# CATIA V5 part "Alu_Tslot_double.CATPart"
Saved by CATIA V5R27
Part number: Tslotted_double
Revision: ANY
Definition: UNKNOWN
Nomenclature: Tslotted_44in
Source: Unknown
Bounding box of the stored display mesh (mm): x -19.05 to 19.05, y -19.05 to 19.05, z -381 to 381
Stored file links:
  \\triton.meca.polymtl.ca\usagers\zaoue\profiles\Desktop\varm_ass\structure prismatique\Alu_Tslot_double.CATPart
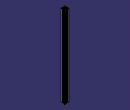
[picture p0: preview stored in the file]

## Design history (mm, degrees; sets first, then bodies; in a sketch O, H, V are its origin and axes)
Body1 "Boss-Extrude1" (main body)
  Solid1: solid without history
  Sketch1 on face of Solid1, origin (0, 19.05, 1524), H (1, 0, 0), V (0, 0, -1)
    point P1 (0, 1524)
    line L1 (-90.0378, 1905) -> (-90.0378, 1143)
    line L2 (-90.0378, 1143) -> (90.0378, 1143)
    line L3 (90.0378, 1143) -> (90.0378, 1905)
    line L4 (90.0378, 1905) -> (-90.0378, 1905)
    reference intersected line E1 through (0, 1524) direction (1, 0) from xy-plane
    reference intersected line E2 through (0, 0) direction (0, 1) from yz-plane
    distance L4 L2 = 762
    vertical: L1 V, L3 V
    horizontal: L2 H, L4 H
    equidistance: L1 L3 P1, L2 L4 P1
    coincidence: E1 P1, P1 E2
  Pocket1: profile Sketch1, direction (0, -1, 0), through (limit type 6), outer side
  Sketch2 on face of Pocket1 from Sketch1.L4, origin (0, 0, -381), H (1, 0, 0), V (0, -1, 0)
    projected arc E1 centre (-15.0939, 19.0563) radius 0.7684 from (-15.8623, 19.05) to (-14.3256, 19.05) ccw from edge [face of Pocket1 from Sketch1.L4 | face of Solid1]
    point P1 (-15.8623, 19.05)
    point P2 (-14.3256, 19.05)
    projected arc E2 centre (-8.7376, 19.05) radius 0.762 from (-9.4996, 19.05) to (-7.9756, 19.05) ccw from edge [face of Pocket1 from Sketch1.L4 | face of Solid1]
    point P3 (-9.4996, 19.05)
    point P4 (-7.9756, 19.05)
    projected arc E3 centre (-19.0564, 15.0939) radius 0.7684 from (-19.05, 14.3256) to (-19.05, 15.8623) ccw from edge [face of Pocket1 from Sketch1.L4 | face of Solid1]
    point P5 (-19.05, 14.3256)
    point P6 (-19.05, 15.8623)
    projected arc E4 centre (-19.05, 8.7376) radius 0.762 from (-19.05, 7.9756) to (-19.05, 9.4996) ccw from edge [face of Pocket1 from Sketch1.L4 | face of Solid1]
    point P7 (-19.05, 7.9756)
    point P8 (-19.05, 9.4996)
    line L1 (-15.8623, 19.05) -> (-14.3256, 19.05)
    reference projected line E5 (-9.4996, 19.05) -> (-14.3256, 19.05) from edge [face of Solid1 | face of Pocket1 from Sketch1.L4]
    line L2 (-9.4996, 19.05) -> (-7.9756, 19.05)
    line L3 (-19.05, 15.8623) -> (-19.05, 14.3256)
    reference projected line E6 (-19.05, 14.3256) -> (-19.05, 9.4996) from edge [face of Solid1 | face of Pocket1 from Sketch1.L4]
    line L4 (-19.05, 9.4996) -> (-19.05, 7.9756)
    reference intersected line E7 through (0, 0) direction (0, 1) from yz-plane
    point P11 (15.8623, 19.05)
    point P12 (14.3256, 19.05)
    point P13 (9.4996, 19.05)
    point P14 (7.9756, 19.05)
    point P15 (19.05, 14.3256)
    point P16 (19.05, 15.8623)
    point P17 (19.05, 7.9756)
    point P18 (19.05, 9.4996)
    line L5 (15.8623, 19.05) -> (14.3256, 19.05)
    line L6 (9.4996, 19.05) -> (7.9756, 19.05)
    line L7 (19.05, 15.8623) -> (19.05, 14.3256)
    line L8 (19.05, 9.4996) -> (19.05, 7.9756)
    arc A1 centre (15.0939, 19.0563) radius 0.7684 from (15.8623, 19.05) to (14.3256, 19.05) cw
    arc A2 centre (8.7376, 19.05) radius 0.762 from (9.4996, 19.05) to (7.9756, 19.05) cw
    arc A3 centre (19.0564, 15.0939) radius 0.7684 from (19.05, 14.3256) to (19.05, 15.8623) cw
    arc A4 centre (19.05, 8.7376) radius 0.762 from (19.05, 7.9756) to (19.05, 9.4996) cw
    reference intersected line E8 through (0, 0) direction (1, 0) from zx-plane
    point P21 (-15.8623, -19.05)
    point P22 (-14.3256, -19.05)
    point P23 (-9.4996, -19.05)
    point P24 (-7.9756, -19.05)
    point P25 (-19.05, -14.3256)
    point P26 (-19.05, -15.8623)
    point P27 (-19.05, -7.9756)
    point P28 (-19.05, -9.4996)
    point P29 (15.8623, -19.05)
    point P30 (14.3256, -19.05)
    point P31 (9.4996, -19.05)
    point P32 (7.9756, -19.05)
    point P33 (19.05, -14.3256)
    point P34 (19.05, -15.8623)
    point P35 (19.05, -7.9756)
    point P36 (19.05, -9.4996)
    line L9 (-15.8623, -19.05) -> (-14.3256, -19.05)
    line L10 (-9.4996, -19.05) -> (-7.9756, -19.05)
    line L11 (-19.05, -15.8623) -> (-19.05, -14.3256)
    line L12 (-19.05, -9.4996) -> (-19.05, -7.9756)
    line L13 (15.8623, -19.05) -> (14.3256, -19.05)
    line L14 (9.4996, -19.05) -> (7.9756, -19.05)
    line L15 (19.05, -15.8623) -> (19.05, -14.3256)
    line L16 (19.05, -9.4996) -> (19.05, -7.9756)
    arc A5 centre (15.0939, -19.0563) radius 0.7684 from (15.8623, -19.05) to (14.3256, -19.05) ccw
    arc A6 centre (8.7376, -19.05) radius 0.762 from (9.4996, -19.05) to (7.9756, -19.05) ccw
    arc A7 centre (19.0564, -15.0939) radius 0.7684 from (19.05, -14.3256) to (19.05, -15.8623) ccw
    arc A8 centre (19.05, -8.7376) radius 0.762 from (19.05, -7.9756) to (19.05, -9.4996) ccw
    arc A9 centre (-15.0939, -19.0563) radius 0.7684 from (-15.8623, -19.05) to (-14.3256, -19.05) cw
    arc A10 centre (-8.7376, -19.05) radius 0.762 from (-9.4996, -19.05) to (-7.9756, -19.05) cw
    arc A11 centre (-19.0564, -15.0939) radius 0.7684 from (-19.05, -14.3256) to (-19.05, -15.8623) cw
    arc A12 centre (-19.05, -8.7376) radius 0.762 from (-19.05, -7.9756) to (-19.05, -9.4996) cw
    horizontal: L1 H, L2 H
    coincidence: L1 E5, L1 L2, L3 E6, L3 L4
    symmetry: P1 P11 E7, P2 P12 E7, P3 P13 E7, P4 P14 E7, P5 P15 E7, P6 P16 E7, P7 P17 E7, P8 P18 E7, E1 A1 E7, E2 A2 E7, E3 A3 E7, E4 A4 E7, L1 L5 E7, L2 L6 E7, L3 L7 E7, L4 L8 E7, P1 P21 E8, P2 P22 E8, P3 P23 E8, P4 P24 E8, P5 P25 E8, P6 P26 E8, P7 P27 E8, P8 P28 E8, P11 P29 E8, P12 P30 E8, P13 P31 E8, P14 P32 E8, P15 P33 E8, P16 P34 E8, P17 P35 E8, P18 P36 E8, E1 A9 E8, E2 A10 E8, E3 A11 E8, E4 A12 E8, L1 L9 E8, L2 L10 E8, L3 L11 E8, L4 L12 E8, L5 L13 E8, L6 L14 E8, L7 L15 E8, L8 L16 E8, A1 A5 E8, A2 A6 E8, A3 A7 E8, A4 A8 E8
  Pad1: profile Sketch2, direction (0, 0, 1), up to face of Pocket1 from Sketch1.L2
